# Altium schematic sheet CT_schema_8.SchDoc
size 274 x 160 mm
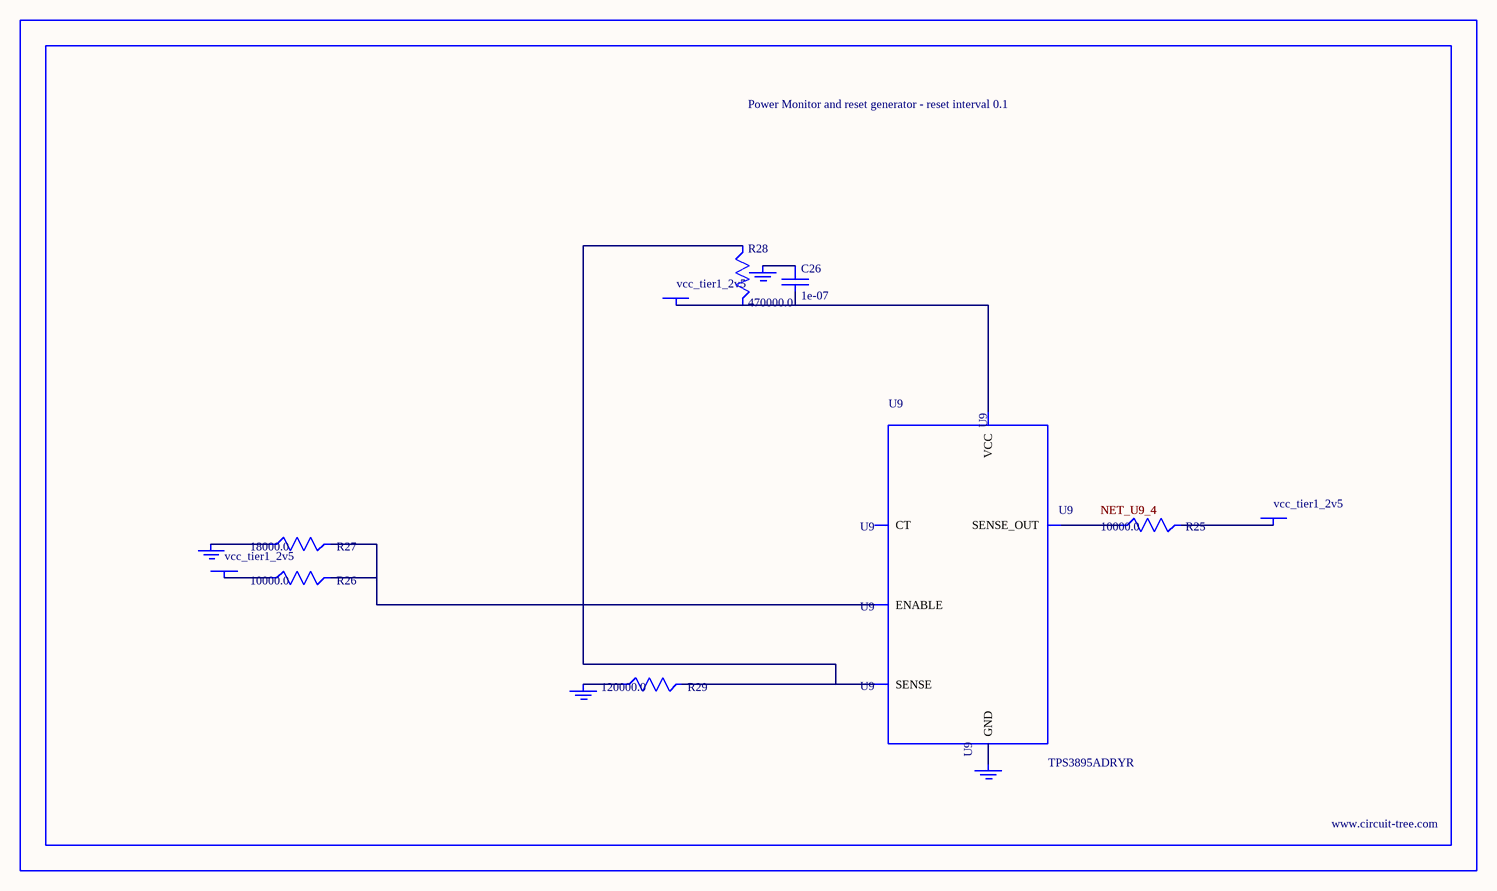
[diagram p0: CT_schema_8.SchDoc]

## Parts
BORDER7  (no value)
C26  1e-07  [C0402]
GND_INSTANCE_7_0  (no value)
GND_INSTANCE_7_1  (no value)
GND_INSTANCE_7_2  (no value)
GND_INSTANCE_7_3  (no value)
POWER_INSTANCE_7_0  vcc_tier1_2v5
POWER_INSTANCE_7_1  vcc_tier1_2v5
POWER_INSTANCE_7_2  vcc_tier1_2v5
R25  10000.0  [R0603]
R26  10000.0  [R0603]
R27  18000.0  [R0603]
R28  470000.0  [R0603]
R29  120000.0  [R0603]
U9  TPS3895ADRYR  [SON-6]

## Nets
NetC26_1: C26.1 GND_INSTANCE_7_2.0(GND)
NetC26_2: C26.2 POWER_INSTANCE_7_2.0(PWR) R28.2 U9.6(VCC)
NetGND_INSTANCE_7_0_0: GND_INSTANCE_7_0.0(GND) R27.1
NetGND_INSTANCE_7_1_0: GND_INSTANCE_7_1.0(GND) R29.1
NetGND_INSTANCE_7_3_0: GND_INSTANCE_7_3.0(GND) U9.2(GND)
NetPOWER_INSTANCE_7_0_0: POWER_INSTANCE_7_0.0(PWR) R26.1
NetPOWER_INSTANCE_7_1_0: POWER_INSTANCE_7_1.0(PWR) R25.2
NetR25_1: R25.1 U9.4(SENSE_OUT)
NetR26_2: R26.2 R27.2 U9.1(ENABLE)
NetR28_1: R28.1 R29.2 U9.3(SENSE)

Not connected (* = marked no-connect by the designer): U9 5(CT)

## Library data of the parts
BORDER7 = BORDER_PAGE7
C26 = C0402C104K3RACTU
GND_INSTANCE_7_0-GND_INSTANCE_7_3 = GND
POWER_INSTANCE_7_0-POWER_INSTANCE_7_2 = PWR
R25 R26 = RC0603JR-0710KL
R27 = RC0603JR-0718KL
R28 = RC0603JR-07470KL
R29 = RC0603JR-07120KL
